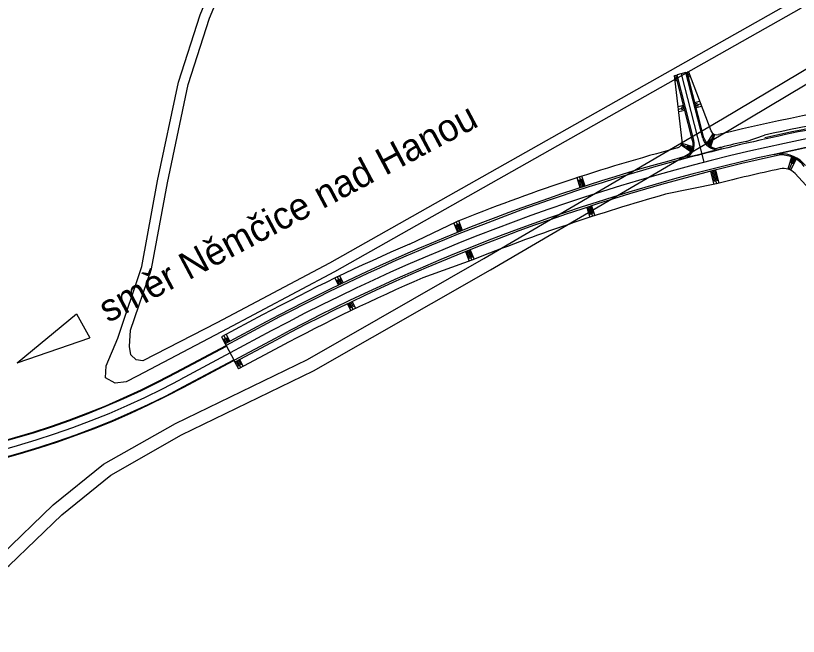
# Model space of a CAD drawing. Extents: x -551750 to -547457, y -1150683 to -1148508.
# Drawn here: x -551581.4 to -551279.8, y -1148985.4 to -1148746.1 of the extents above; entities that cross this region are included whole.
import ezdxf

# ---------------------------------------------------------------- set-up
doc = ezdxf.new("R2010")
doc.units = 0
for name, color, linetype in [('D02_ZaplUzemi20Vody', 7, 'Continuous'), ('D03_ZaplUzemi100Vody', 7, 'Continuous'), ('u_popis_5000', 7, 'Continuous'), ('u_trat navrh', 7, 'Continuous')]:
    doc.layers.add(name, color=color, linetype=linetype)

msp = doc.modelspace()

# ---------------------------------------------------------------- linework, layer by layer
at = {"layer": 'D02_ZaplUzemi20Vody'}
for points in [[(-551216.64, -1148707.16), (-551280.57, -1148739.81), (-551460.38, -1148841.52), (-551503.9, -1148864.57), (-551532.34, -1148879.18), (-551534.91, -1148878.74), (-551536.95, -1148876.82), (-551537.47, -1148873.61), (-551537.08, -1148867.34), (-551529.01, -1148843.76), (-551522.87, -1148810.57), (-551514.86, -1148772.71), (-551506.67, -1148747.16), (-551499.28, -1148729.08), (-551491.36, -1148709.06), (-551481.77, -1148696.67), (-551472.71, -1148689.97), (-551456.13, -1148682.51), (-551365.71, -1148649.22), (-551298.12, -1148624.39), (-551282.1, -1148621.66), (-551266.42, -1148624.01)], [(-551750.39, -1148974.53), (-551730.07, -1148979.32), (-551689.87, -1148985.39), (-551658.59, -1148985.39), (-551628.53, -1148982.3), (-551605.62, -1148973.61), (-551583.86, -1148958.06), (-551563.57, -1148938.51), (-551544.63, -1148923.2), (-551517.47, -1148907.77), (-551466.63, -1148883.09), (-551398.44, -1148844.1), (-551306.46, -1148790.22), (-551247.22, -1148754.96)]]:
    msp.add_lwpolyline(points, dxfattribs=at)
at = {"layer": 'D03_ZaplUzemi100Vody'}
for points in [[(-551278.69, -1148743.2), (-551458.52, -1148844.93), (-551502.09, -1148868.01), (-551534.55, -1148885.1), (-551538.82, -1148887.24), (-551543.03, -1148887.73), (-551546.69, -1148885.77), (-551546.45, -1148881.13), (-551542.05, -1148870.39), (-551532.78, -1148842.79), (-551526.68, -1148809.82), (-551518.62, -1148771.72), (-551510.32, -1148745.83), (-551502.88, -1148727.63), (-551494.76, -1148707.12), (-551484.51, -1148693.87), (-551474.69, -1148686.6), (-551457.6, -1148678.91), (-551367.05, -1148645.57), (-551299.56, -1148620.78), (-551272.22, -1148610.1)], [(-551750.39, -1148969.37), (-551729.11, -1148974.37), (-551689.5, -1148980.36), (-551658.85, -1148980.36), (-551629.7, -1148977.37), (-551608.02, -1148969.14), (-551587.09, -1148954.18), (-551566.91, -1148934.73), (-551547.47, -1148919.03), (-551519.81, -1148903.32), (-551468.98, -1148878.64), (-551400.96, -1148839.74), (-551309.02, -1148785.89), (-551249.96, -1148750.74)]]:
    msp.add_lwpolyline(points, dxfattribs=at)
at = {"layer": 'u_popis_5000'}
msp.add_line((-551557.92, -1148861.12), (-551552.78, -1148870.28), dxfattribs=at)
for points in [[(-551580.74, -1148879.95), (-551557.92, -1148861.12)], [(-551580.74, -1148879.95), (-551552.78, -1148870.28)]]:
    msp.add_lwpolyline(points, dxfattribs=at)
at = {"layer": 'u_trat navrh'}
for p, q in [((-551327.51, -1148769.2), (-551327.02, -1148769.08)), ((-551324.51, -1148794.38), (-551327.51, -1148769.2)), ((-551327.39, -1148770.21), (-551326.77, -1148770.05)), ((-551327.17, -1148769.63), (-551326.9, -1148769.56)), ((-551327.02, -1148769.08), (-551326.54, -1148768.95)), ((-551320.53, -1148794.3), (-551327.02, -1148769.08)), ((-551323.15, -1148768.08), (-551326.54, -1148768.95)), ((-551320.05, -1148794.17), (-551326.54, -1148768.95)), ((-551316.06, -1148802.66), (-551324.84, -1148768.52)), ((-551323.15, -1148768.08), (-551322.66, -1148767.96)), ((-551316.66, -1148793.3), (-551323.15, -1148768.08)), ((-551322.18, -1148767.83), (-551322.66, -1148767.96)), ((-551316.18, -1148793.17), (-551322.66, -1148767.96)), ((-551322.27, -1148768.37), (-551322.54, -1148768.44)), ((-551321.82, -1148768.77), (-551322.41, -1148768.93)), ((-551321.96, -1148769.33), (-551322.29, -1148769.41)), ((-551322.18, -1148767.83), (-551313.49, -1148790.46)), ((-551321.46, -1148769.71), (-551322.16, -1148769.9)), ((-551327.27, -1148771.21), (-551326.52, -1148771.02)), ((-551326.99, -1148770.62), (-551326.65, -1148770.53)), ((-551319.67, -1148779.6), (-551317.84, -1148779.13)), ((-551324.03, -1148780.72), (-551326.07, -1148781.25)), ((-551323.78, -1148781.69), (-551325.96, -1148782.25)), ((-551323.9, -1148781.2), (-551324.96, -1148781.48)), ((-551323.65, -1148782.17), (-551324.77, -1148782.46)), ((-551319.54, -1148780.08), (-551318.6, -1148779.84)), ((-551319.42, -1148780.57), (-551317.48, -1148780.07)), ((-551319.29, -1148781.05), (-551318.3, -1148780.8)), ((-551319.17, -1148781.54), (-551317.12, -1148781.01)), ((-551323.53, -1148782.66), (-551325.84, -1148783.25)), ((-551315.06, -1148795.35), (-551312.56, -1148791.64)), ((-551314.72, -1148795.71), (-551313.56, -1148793.72)), ((-551314.35, -1148796.05), (-551312.26, -1148791.81)), ((-551313.95, -1148796.35), (-551313.03, -1148794.11)), ((-551313.52, -1148796.61), (-551311.95, -1148791.94)), ((-551299.9, -1148794.58), (-551292.88, -1148792.22)), ((-551321.2, -1148798.59), (-551324.92, -1148796.08)), ((-551320.75, -1148797.7), (-551324.75, -1148795.77)), ((-551320.46, -1148796.74), (-551324.61, -1148795.43)), ((-551320.95, -1148798.15), (-551322.89, -1148797.04)), ((-551320.58, -1148797.22), (-551322.63, -1148796.41)), ((-551309.41, -1148797.63), (-551309.45, -1148797.49)), ((-551289.15, -1148799.59), (-551289.12, -1148799.73)), ((-551324.3, -1148801.46), (-551324.34, -1148801.32)), ((-551282.47, -1148800.57), (-551283.84, -1148805.26)), ((-551281.55, -1148800.96), (-551283.31, -1148805.44)), ((-551280.67, -1148801.44), (-551282.81, -1148805.67)), ((-551282.01, -1148800.75), (-551282.79, -1148803.05)), ((-551281.11, -1148801.19), (-551282.08, -1148803.37)), ((-551313.6, -1148806.16), (-551312.33, -1148811.2)), ((-551313.12, -1148806.03), (-551312.09, -1148810.1)), ((-551312.64, -1148805.91), (-551311.36, -1148810.95)), ((-551312.15, -1148805.79), (-551311.12, -1148809.86)), ((-551311.67, -1148805.67), (-551310.39, -1148810.71)), ((-551363.83, -1148812.44), (-551365.07, -1148808.64)), ((-551364.12, -1148808.33), (-551362.88, -1148812.13)), ((-551362.4, -1148811.98), (-551363.33, -1148809.12)), ((-551361.93, -1148811.82), (-551363.16, -1148808.02)), ((-551255.19, -1148835.21), (-551281.09, -1148806.97)), ((-551363.35, -1148812.29), (-551364.28, -1148809.44)), ((-551361.35, -1148820.05), (-551360.1, -1148823.85)), ((-551360.87, -1148819.89), (-551359.94, -1148822.75)), ((-551360.4, -1148819.74), (-551359.16, -1148823.54)), ((-551359.92, -1148819.58), (-551358.99, -1148822.44)), ((-551359.45, -1148819.43), (-551358.21, -1148823.23)), ((-551429.67, -1148834.2), (-551411.6, -1148825.58)), ((-551411.04, -1148829.67), (-551412.51, -1148826.02)), ((-551410.58, -1148829.48), (-551411.7, -1148826.7)), ((-551411.6, -1148825.58), (-551410.11, -1148829.29)), ((-551409.65, -1148829.11), (-551410.77, -1148826.32)), ((-551409.19, -1148828.92), (-551410.67, -1148825.21)), ((-551406.67, -1148836.53), (-551405.55, -1148839.32)), ((-551406.21, -1148836.35), (-551404.72, -1148840.06)), ((-551408.06, -1148837.09), (-551406.58, -1148840.77)), ((-551407.6, -1148836.9), (-551406.48, -1148839.69)), ((-551407.13, -1148836.72), (-551405.64, -1148840.43)), ((-551457, -1148850), (-551458.31, -1148847.3)), ((-551456.55, -1148849.78), (-551457.42, -1148847.98)), ((-551456.1, -1148849.56), (-551457.4, -1148846.86)), ((-551455.65, -1148849.35), (-551456.52, -1148847.54)), ((-551455.2, -1148849.13), (-551456.5, -1148846.42)), ((-551453.54, -1148857.21), (-551452.23, -1148859.91)), ((-551453.08, -1148856.99), (-551452.22, -1148858.79)), ((-551451.33, -1148859.48), (-551452.63, -1148856.77)), ((-551452.18, -1148856.56), (-551451.32, -1148858.36)), ((-551451.73, -1148856.34), (-551450.44, -1148859.04)), ((-551484.79, -1148864.13), (-551500.66, -1148872.62)), ((-551484.43, -1148864.79), (-551500.3, -1148873.28)), ((-551501.19, -1148869.5), (-551499.78, -1148872.14)), ((-551500.31, -1148869.03), (-551498.89, -1148871.67)), ((-551502.07, -1148869.97), (-551500.66, -1148872.62)), ((-551501.16, -1148870.62), (-551500.22, -1148872.38)), ((-551500.66, -1148872.62), (-551500.3, -1148873.28)), ((-551500.28, -1148870.14), (-551499.34, -1148871.91)), ((-551481.37, -1148870.52), (-551497.24, -1148879.01)), ((-551481.01, -1148871.18), (-551496.89, -1148879.67)), ((-551519.63, -1148883.61), (-551500.3, -1148873.28)), ((-551519.52, -1148883.84), (-551500.19, -1148873.5)), ((-551500.3, -1148873.28), (-551500.19, -1148873.5)), ((-551500.19, -1148873.5), (-551497.36, -1148878.79)), ((-551498.77, -1148876.14), (-551518.1, -1148886.48)), ((-551495.12, -1148878.73), (-551493.71, -1148881.37)), ((-551516.69, -1148889.13), (-551497.36, -1148878.79)), ((-551516.57, -1148889.35), (-551497.24, -1148879.01)), ((-551497.36, -1148878.79), (-551497.24, -1148879.01)), ((-551497.24, -1148879.01), (-551496.89, -1148879.67)), ((-551496.89, -1148879.67), (-551495.47, -1148882.31)), ((-551496.44, -1148879.43), (-551495.5, -1148881.2)), ((-551496, -1148879.2), (-551494.59, -1148881.84)), ((-551495.56, -1148878.96), (-551494.62, -1148880.73))]:
    msp.add_line(p, q, dxfattribs=at)
for points in [[(-551311.36, -1148810.95), (-551331, -1148814.98)], [(-551405.64, -1148840.43), (-551424.5, -1148847.21)], [(-551486.2, -1148861.48), (-551502.07, -1148869.97)], [(-551482.9, -1148867.65), (-551498.77, -1148876.14)], [(-551479.6, -1148873.83), (-551495.47, -1148882.31)]]:
    msp.add_lwpolyline(points, dxfattribs=at)
for centre, radius, start, end in [((-551129.18, -1149529), 750, 82.52854, 118.14007), ((-551129.18, -1149529), 759, 98.10484, 103.82611), ((-551129.18, -1149529), 753.25, 97.69742, 103.84377), ((-551129.18, -1149529), 754.75, 98.36945, 102.52692), ((-551129.18, -1149529), 753.75, 98.21006, 102.52692), ((-551311.16, -1148789.57), 2.5, 201.0007, 283.8261), ((-551325.86, -1148795.67), 6, 297.8016, 14.4286), ((-551325.86, -1148795.67), 5.5, 302.293, 14.4286), ((-551310.85, -1148791.81), 6, 194.4286, 271.0556), ((-551310.85, -1148791.81), 5.5, 194.4286, 266.5643), ((-551129.18, -1149529), 746.75, 99.42768, 102.36984), ((-551129.18, -1149529), 746.6, 99.42768, 102.36984), ((-551129.18, -1149529), 758, 105.07699, 111.87573), ((-551327, -1148794.68), 2.5, 285.077, 6.7733), ((-551129.18, -1149529), 754, 103.84377, 103.96791), ((-551129.18, -1149529), 754, 103.08634, 103.84377), ((-551129.18, -1149529), 746.75, 102.36984, 118.14007), ((-551129.18, -1149529), 746, 102.36984, 118.14007), ((-551129.18, -1149529), 754, 104.88933, 105.01348), ((-551129.18, -1149529), 753.4, 103.84377, 105.01348), ((-551129.18, -1149529), 753.25, 103.84377, 105.01348), ((-551129.18, -1149529), 746, 102.18528, 102.36984), ((-551286.58, -1148811.31), 12, 37.8838, 93.2277), ((-551286.58, -1148811.31), 11.5, 37.8838, 90.3085), ((-551129.18, -1149529), 754, 105.01348, 118.14007), ((-551129.18, -1149529), 753.25, 105.01348, 118.14007), ((-551129.18, -1149529), 740.8, 102.28396, 104.23629), ((-551285.51, -1148811.02), 6, 42.5226, 102.284), ((-551129.18, -1149529), 742, 105.78315, 111.87573), ((-551129.18, -1149529), 757, 113.38749, 118.14007), ((-551129.18, -1149529), 743, 113.42009, 118.14007), ((-551669.02, -1148604.3), 316.75, 255.1142, 298.1401), ((-551669.02, -1148604.3), 317, 255.1262, 298.1401), ((-551669.02, -1148604.3), 320, 255.2688, 298.1401), ((-551669.02, -1148604.3), 323, 255.4087, 298.1401), ((-551669.02, -1148604.3), 323.25, 255.4202, 298.1401)]:
    msp.add_arc(centre, radius, start, end, dxfattribs=at)

# ---------------------------------------------------------------- texts
at = {"layer": 'u_popis_5000'}
msp.add_text('směr Němčice nad Hanou', height=10.5, rotation=27.9909, dxfattribs=at).set_placement((-551545.76, -1148864.7))

doc.saveas('drawing.dxf')
